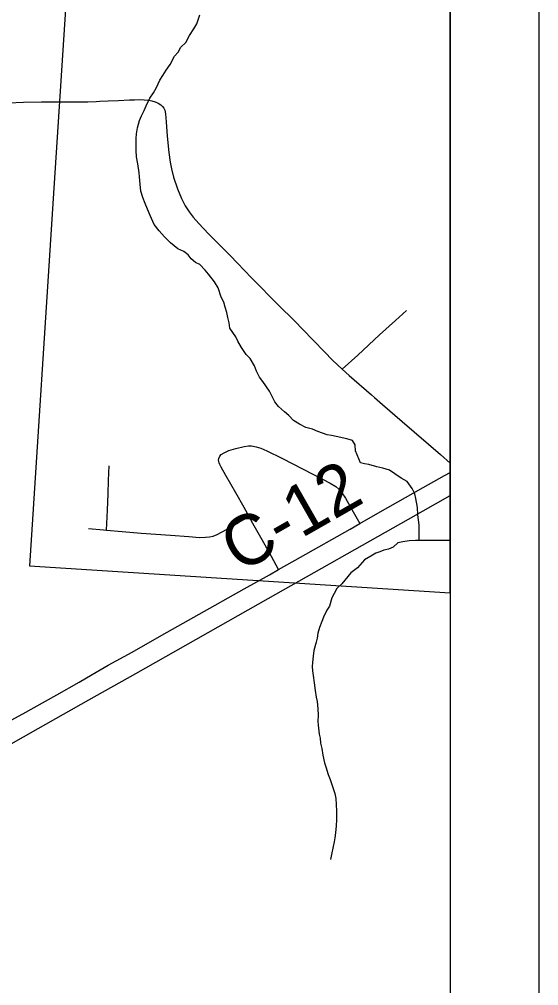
# Model space of a CAD drawing. Extents: x -8.2 to 34, y 0 to 22.
# Drawn here: x 8.412 to 9, y 15.949 to 17.043 of the extents above; entities that cross this region are included whole.
import ezdxf

# ---------------------------------------------------------------- set-up
doc = ezdxf.new("R2010")
doc.units = 0
for name, color, linetype in [('GM_X_Corporation', 7, 'Continuous'), ('GM_X_County_Road', 7, 'Continuous'), ('GM_X_County_Road_Text', 7, 'Continuous'), ('GM_X_Minor_River', 7, 'Continuous'), ('GM_X_Township_Road', 7, 'Continuous'), ('GM_X_US_Route', 7, 'Continuous'), ('SH_Data', 7, 'Continuous')]:
    doc.layers.add(name, color=color, linetype=linetype)

msp = doc.modelspace()

# ---------------------------------------------------------------- linework, layer by layer
at = {"layer": 'GM_X_Corporation'}
msp.add_lwpolyline([(8.9, 16.3939), (8.9, 17.4413), (8.4898, 17.4646), (8.4777, 17.2575), (8.4507, 16.8404), (8.4238, 16.4247)], close=True, dxfattribs=at)
at = {"layer": 'GM_X_County_Road'}
msp.add_lwpolyline([(8.4031, 16.25), (8.4161, 16.2572), (8.4547, 16.2786), (8.4801, 16.293), (8.4946, 16.3015), (8.5129, 16.312), (8.5401, 16.3269), (8.5736, 16.346), (8.6157, 16.3697), (8.6666, 16.3984), (8.6953, 16.4145), (8.7056, 16.4203), (8.7304, 16.4345), (8.7866, 16.4662), (8.7975, 16.4724), (8.8207, 16.4855), (8.8693, 16.5131), (8.8936, 16.5267), (8.9, 16.5302)], dxfattribs=at)
at = {"layer": 'GM_X_Minor_River'}
for points in [[(8.8649, 16.4534), (8.8648, 16.4709), (8.8634, 16.4823), (8.8627, 16.4907), (8.8608, 16.5006), (8.8597, 16.5059), (8.8567, 16.512), (8.851, 16.52), (8.8442, 16.5239), (8.8374, 16.5288), (8.831, 16.5327), (8.8237, 16.535), (8.8169, 16.5366), (8.8078, 16.5393), (8.8029, 16.5401), (8.7983, 16.5412), (8.7927, 16.5546), (8.7923, 16.5614), (8.7893, 16.5664), (8.7829, 16.5683), (8.7707, 16.571), (8.7654, 16.5722), (8.7608, 16.573), (8.7502, 16.5765), (8.7441, 16.5792), (8.7365, 16.5811), (8.7293, 16.585), (8.7225, 16.5892), (8.7172, 16.5949), (8.7123, 16.5987), (8.7055, 16.6049), (8.7013, 16.6102), (8.6953, 16.6224), (8.6878, 16.6331), (8.684, 16.6381), (8.6806, 16.6449), (8.6784, 16.651), (8.6735, 16.6594), (8.6689, 16.6637), (8.6637, 16.6717), (8.6595, 16.6789), (8.6573, 16.6839), (8.6539, 16.6885), (8.6505, 16.6934), (8.6497, 16.6995), (8.6483, 16.7056), (8.6471, 16.7113), (8.6453, 16.7174), (8.6438, 16.7231), (8.6408, 16.7285), (8.6374, 16.7392), (8.6333, 16.746), (8.6265, 16.7548), (8.6227, 16.7594), (8.6167, 16.7655), (8.6117, 16.7678), (8.6068, 16.772), (8.6034, 16.7766), (8.5985, 16.7805), (8.5917, 16.7835), (8.5833, 16.79), (8.5765, 16.7969), (8.5705, 16.8038), (8.5648, 16.8111), (8.5603, 16.821), (8.5573, 16.8282), (8.5547, 16.8347), (8.5521, 16.8416), (8.5498, 16.8488), (8.5491, 16.8564), (8.5484, 16.8648), (8.5477, 16.8694), (8.5462, 16.8797), (8.5447, 16.8877), (8.5444, 16.8945), (8.5445, 16.9082), (8.5449, 16.9135), (8.546, 16.9204), (8.5484, 16.9287), (8.5507, 16.9341), (8.5534, 16.9401), (8.5557, 16.9451), (8.5599, 16.9538), (8.5641, 16.9599), (8.5676, 16.9659), (8.5711, 16.9743), (8.5745, 16.9796), (8.5784, 16.9857), (8.583, 16.9921), (8.588, 17.0016), (8.5922, 17.0061), (8.5952, 17.0115), (8.6006, 17.0171), (8.6048, 17.0247), (8.6098, 17.0323), (8.6133, 17.038), (8.6167, 17.0483)], [(8.9, 16.4532), (8.8944, 16.4532), (8.8864, 16.4533), (8.8605, 16.4534), (8.8533, 16.453), (8.8461, 16.4519), (8.8407, 16.4504), (8.8354, 16.4455), (8.8301, 16.4436), (8.8247, 16.4422), (8.8202, 16.4403), (8.8156, 16.4388), (8.8099, 16.4354), (8.803, 16.4312), (8.795, 16.4221), (8.7873, 16.4168), (8.7774, 16.4043), (8.7716, 16.399), (8.7686, 16.3934), (8.7659, 16.3884), (8.7631, 16.3789), (8.7601, 16.3744), (8.7566, 16.3664), (8.7547, 16.3615), (8.752, 16.3546), (8.75, 16.3485), (8.7492, 16.3428), (8.7481, 16.3383), (8.7457, 16.3288), (8.7449, 16.3223), (8.7441, 16.3151), (8.7437, 16.3105), (8.7441, 16.3056), (8.7448, 16.3006), (8.7459, 16.2922), (8.747, 16.2835), (8.7481, 16.2759), (8.7492, 16.2709), (8.7499, 16.2625), (8.7503, 16.2557), (8.7502, 16.2488), (8.7506, 16.2443), (8.7517, 16.234), (8.7528, 16.2294), (8.7531, 16.2237), (8.7546, 16.2176), (8.7557, 16.2104), (8.7576, 16.2016), (8.7591, 16.197), (8.7617, 16.1883), (8.7639, 16.1826), (8.7654, 16.178), (8.7692, 16.1669), (8.7703, 16.1612), (8.771, 16.1544), (8.7713, 16.1468), (8.7713, 16.1369), (8.7709, 16.1304), (8.77, 16.1224), (8.7693, 16.1167), (8.7685, 16.1121), (8.7673, 16.1068), (8.7657, 16.0977), (8.7645, 16.092)]]:
    msp.add_lwpolyline(points, dxfattribs=at)
at = {"layer": 'GM_X_Township_Road'}
for points in [[(8.4001, 16.9488), (8.4168, 16.9494), (8.4372, 16.9497), (8.4632, 16.9496), (8.4769, 16.9497), (8.4899, 16.9499), (8.4992, 16.9502), (8.5033, 16.9504), (8.5128, 16.9508), (8.5246, 16.9513), (8.537, 16.9519), (8.5425, 16.9522), (8.5487, 16.9523), (8.5536, 16.9521), (8.5585, 16.9517), (8.5623, 16.951), (8.5661, 16.9497), (8.5694, 16.9481), (8.5724, 16.9463), (8.5742, 16.9446), (8.5758, 16.9425), (8.5771, 16.9403), (8.5778, 16.9362), (8.5785, 16.9272), (8.5796, 16.9111), (8.5813, 16.8925), (8.5829, 16.8814), (8.5844, 16.874), (8.5869, 16.8644), (8.5912, 16.8513), (8.5957, 16.8403), (8.6001, 16.832), (8.6045, 16.8252), (8.6091, 16.8193), (8.6153, 16.8122), (8.6265, 16.8005), (8.6509, 16.7758), (8.659, 16.7673), (8.6672, 16.7588), (8.6749, 16.7507), (8.6855, 16.7398), (8.6956, 16.7293), (8.7049, 16.7202), (8.7243, 16.701), (8.7327, 16.6926), (8.7577, 16.6669), (8.7668, 16.6574), (8.7775, 16.6473), (8.7856, 16.6401), (8.8107, 16.6181), (8.8142, 16.615), (8.8233, 16.607), (8.8455, 16.5881), (8.889, 16.5505), (8.9, 16.5408)], [(8.7775, 16.6473), (8.7953, 16.6632), (8.8199, 16.6859), (8.8381, 16.7023), (8.8505, 16.7137)], [(8.7056, 16.4203), (8.6976, 16.4351), (8.6871, 16.4538), (8.6766, 16.4723), (8.6722, 16.4805), (8.6667, 16.4905), (8.6571, 16.5071), (8.6461, 16.5268), (8.6406, 16.5363), (8.639, 16.5391), (8.6384, 16.5413), (8.6378, 16.544), (8.6382, 16.5459), (8.6392, 16.5486), (8.6408, 16.5504), (8.644, 16.5526), (8.6495, 16.555), (8.6571, 16.5575), (8.6667, 16.5597), (8.6715, 16.5604), (8.675, 16.5603), (8.6804, 16.5591), (8.6857, 16.5576), (8.6925, 16.5548), (8.7092, 16.5466), (8.745, 16.5279), (8.7561, 16.5224), (8.764, 16.5182), (8.7705, 16.5142), (8.7737, 16.5114), (8.7772, 16.5073), (8.7813, 16.5011), (8.7899, 16.4856), (8.7975, 16.4724)], [(8.5109, 16.4649), (8.512, 16.4875), (8.5128, 16.5062), (8.5133, 16.5211), (8.5141, 16.5378)], [(8.4905, 16.4667), (8.5075, 16.4653), (8.5109, 16.4649), (8.5285, 16.4633), (8.5501, 16.4617), (8.5835, 16.4593), (8.6039, 16.4577), (8.6163, 16.4568), (8.6231, 16.4569), (8.6276, 16.4574), (8.6317, 16.4582), (8.6362, 16.4599), (8.6468, 16.4658), (8.6602, 16.4737), (8.6722, 16.4805)]]:
    msp.add_lwpolyline(points, dxfattribs=at)
at = {"layer": 'GM_X_US_Route'}
msp.add_lwpolyline([(8.0473, 16.0261), (8.0488, 16.0268), (8.0968, 16.0513), (8.1286, 16.0683), (8.1337, 16.0712), (8.1946, 16.1055), (8.2482, 16.1356), (8.3196, 16.1759), (8.4337, 16.2405), (8.491, 16.2729), (8.544, 16.3028), (8.6939, 16.3874), (8.8528, 16.4774), (8.9, 16.504)], dxfattribs=at)
at = {"layer": 'SH_Data'}
for p, q in [((9, 21), (9, 14)), ((8.9, 20.9), (8.9, 14.1))]:
    msp.add_line(p, q, dxfattribs=at)

# ---------------------------------------------------------------- texts
at = {"layer": 'GM_X_County_Road_Text'}
msp.add_text('C-12', height=0.05682, rotation=29.7441, dxfattribs=at).set_placement((8.6617, 16.4156))

doc.saveas('drawing.dxf')
